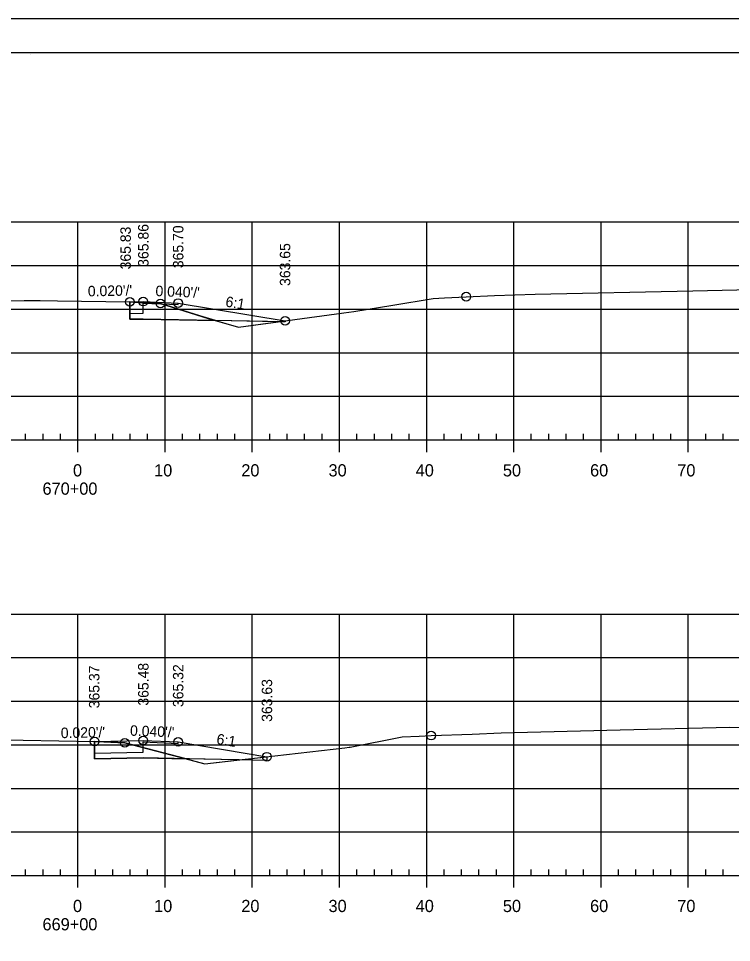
# Model space of a CAD drawing. Extents: x 1359801 to 1362404, y 372415 to 374228.
# Drawn here: x 1361813.1 to 1361894.9, y 373908.6 to 374014.6 of the extents above; entities that cross this region are included whole.
import ezdxf

# ---------------------------------------------------------------- set-up
doc = ezdxf.new("R2010")
doc.units = 0
for name, color, linetype in [('S_DRG_PT_SYM', 7, 'Continuous'), ('S_ELECTRIC_UTILITIES_ANNOT', 7, 'Continuous'), ('S_IRON_PIN', 7, 'Continuous'), ('S_MAILBOX', 7, 'Continuous'), ('S_PRIMARY_CTL', 7, 'Continuous'), ('S_SANITARY_SEWER', 7, 'Continuous'), ('S_SHOULDER', 7, 'Continuous'), ('S_UNDERGROUND_CABLE', 7, 'Continuous'), ('S_UTL_PT_SYM', 7, 'Continuous'), ('S_WATER_UTILITIES', 7, 'Continuous')]:
    doc.layers.add(name, color=color, linetype=linetype)

msp = doc.modelspace()

# ---------------------------------------------------------------- linework, layer by layer
at = {"layer": 'S_DRG_PT_SYM'}
for points in [[(1361805.02, 373982.16), (1361813.73, 373982.25), (1361815.57, 373982.27), (1361817.55, 373982.24), (1361825.85, 373982.1), (1361826.99, 373982.04), (1361829.35, 373981.92), (1361834.83, 373980.21), (1361838.31, 373979.2), (1361850.39, 373980.85), (1361851.53, 373981), (1361855.99, 373981.73), (1361860.64, 373982.48), (1361861.95, 373982.57), (1361864.43, 373982.7), (1361867.66, 373982.82), (1361872.35, 373982.98), (1361890.4, 373983.37), (1361898.81, 373983.56)], [(1361811.72, 373931.84), (1361813.61, 373931.8), (1361821.81, 373931.64), (1361822.85, 373931.6), (1361825.26, 373931.49), (1361831.41, 373929.89), (1361834.46, 373929.09), (1361850.51, 373930.92), (1361851.01, 373930.98), (1361851.1, 373930.99), (1361857.07, 373932.17), (1361859.03, 373932.26), (1361860.39, 373932.32), (1361865.12, 373932.5), (1361868.43, 373932.63), (1361882.09, 373932.98), (1361894.64, 373933.28), (1361902.31, 373933.15), (1361921.1, 373932.76), (1361940.7, 373933.16), (1361943.77, 373933.22), (1361944.16, 373933.23), (1361947.51, 373933.14), (1361964.89, 373932.7)]]:
    msp.add_lwpolyline(points, dxfattribs=at)
at = {"layer": 'S_ELECTRIC_UTILITIES_ANNOT'}
for p, q in [((1361833.88, 373980.5), (1361829.35, 373981.92)), ((1361842.87, 373979.82), (1361835.66, 373979.97)), ((1361835.66, 373979.97), (1361835.66, 373979.97)), ((1361842.87, 373979.82), (1361842.87, 373979.82)), ((1361832.3, 373929.66), (1361825.26, 373931.49)), ((1361838.4, 373929.54), (1361832.3, 373929.66)), ((1361832.3, 373929.66), (1361832.3, 373929.66)), ((1361838.4, 373929.54), (1361838.4, 373929.54))]:
    msp.add_line(p, q, dxfattribs=at)
for points in [[(1361829.35, 373981.92), (1361826.99, 373982.04), (1361825.85, 373982.1)], [(1361825.85, 373982.1), (1361825.85, 373980.6), (1361825.85, 373980.1), (1361827.39, 373980.13), (1361835.66, 373979.97), (1361833.88, 373980.5)], [(1361835.66, 373979.97), (1361838.31, 373979.2), (1361842.87, 373979.82)], [(1361825.26, 373931.49), (1361822.85, 373931.6), (1361821.81, 373931.64)], [(1361821.81, 373931.64), (1361821.81, 373929.64), (1361827.39, 373929.76), (1361832.3, 373929.66)], [(1361832.3, 373929.66), (1361834.46, 373929.09), (1361838.4, 373929.54)]]:
    msp.add_lwpolyline(points, dxfattribs=at)
for points in [[(1361842.87, 373979.82), (1361843.65, 373979.93), (1361843.65, 373979.81)], [(1361838.4, 373929.54), (1361841.57, 373929.9), (1361841.57, 373929.47)]]:
    msp.add_lwpolyline(points, close=True, dxfattribs=at)
at = {"layer": 'S_MAILBOX'}
for p, q in [((1361674.89, 373991.27), (1361964.89, 373991.27)), ((1361819.89, 373966.27), (1361819.89, 373991.27)), ((1361829.89, 373966.27), (1361829.89, 373991.27)), ((1361839.89, 373966.27), (1361839.89, 373991.27)), ((1361849.89, 373966.27), (1361849.89, 373991.27)), ((1361859.89, 373966.27), (1361859.89, 373991.27)), ((1361869.89, 373966.27), (1361869.89, 373991.27)), ((1361879.89, 373966.27), (1361879.89, 373991.27)), ((1361889.89, 373966.27), (1361889.89, 373991.27)), ((1361674.89, 373986.27), (1361964.89, 373986.27)), ((1361674.89, 373981.27), (1361964.89, 373981.27)), ((1361674.89, 373976.27), (1361964.89, 373976.27)), ((1361674.89, 373971.27), (1361964.89, 373971.27)), ((1361674.89, 373966.27), (1361964.89, 373966.27)), ((1361674.89, 373946.27), (1361964.89, 373946.27)), ((1361819.89, 373916.27), (1361819.89, 373946.27)), ((1361829.89, 373916.27), (1361829.89, 373946.27)), ((1361839.89, 373916.27), (1361839.89, 373946.27)), ((1361849.89, 373916.27), (1361849.89, 373946.27)), ((1361859.89, 373916.27), (1361859.89, 373946.27)), ((1361869.89, 373916.27), (1361869.89, 373946.27)), ((1361879.89, 373916.27), (1361879.89, 373946.27)), ((1361889.89, 373916.27), (1361889.89, 373946.27)), ((1361674.89, 373941.27), (1361964.89, 373941.27)), ((1361674.89, 373936.27), (1361964.89, 373936.27)), ((1361674.89, 373931.27), (1361964.89, 373931.27)), ((1361674.89, 373926.27), (1361964.89, 373926.27)), ((1361674.89, 373921.27), (1361964.89, 373921.27)), ((1361674.89, 373916.27), (1361964.89, 373916.27))]:
    msp.add_line(p, q, dxfattribs=at)
at = {"layer": 'S_SANITARY_SEWER'}
for points in [[(1361825.85, 373982.1), (1361827.39, 373982.13), (1361831.39, 373981.97), (1361843.65, 373979.93)], [(1361821.81, 373931.64), (1361827.39, 373931.76), (1361831.39, 373931.6), (1361841.57, 373929.9)]]:
    msp.add_lwpolyline(points, dxfattribs=at)
at = {"layer": 'S_SHOULDER'}
for p, q in [((1361649.49, 374014.63), (1361982.82, 374014.63)), ((1361843.65, 373979.93), (1361843.65, 373979.81)), ((1361843.65, 373979.81), (1361843.65, 373979.81)), ((1361841.57, 373929.9), (1361841.57, 373929.47)), ((1361841.57, 373929.47), (1361841.58, 373929.47))]:
    msp.add_line(p, q, dxfattribs=at)
for points in [[(1361649.48, 374014.63), (1361982.82, 374014.63), (1361982.82, 373801.29), (1361649.48, 373801.29)], [(1361895.81, 374010.73), (1361895.81, 374000.85), (1361931.54, 374000.85), (1361931.54, 373997.93), (1361954.74, 373997.93), (1361954.74, 373973.6), (1361978.07, 373973.6), (1361978.07, 373805.27), (1361661.89, 373805.27), (1361661.89, 374010.73)]]:
    msp.add_lwpolyline(points, close=True, dxfattribs=at)
for points in [[(1361825.85, 373980.77), (1361827.39, 373980.8), (1361827.39, 373981.96)], [(1361827.39, 373981.96), (1361831.37, 373981.8), (1361831.39, 373981.97), (1361843.65, 373979.93)], [(1361843.65, 373979.81), (1361827.39, 373980.13), (1361825.85, 373980.1), (1361825.85, 373980.77)], [(1361821.81, 373930.31), (1361827.39, 373930.42), (1361827.39, 373931.59)], [(1361827.39, 373931.59), (1361831.37, 373931.43), (1361831.39, 373931.6), (1361841.57, 373929.9)], [(1361841.58, 373929.47), (1361827.39, 373929.76), (1361821.81, 373929.64), (1361821.81, 373930.31)]]:
    msp.add_lwpolyline(points, dxfattribs=at)
for centre in [(1361864.43, 373982.7), (1361825.85, 373982.1), (1361827.39, 373982.13), (1361829.35, 373981.92), (1361831.39, 373981.97), (1361843.65, 373979.93), (1361821.81, 373931.64), (1361827.39, 373931.76), (1361860.39, 373932.32), (1361825.26, 373931.49), (1361831.39, 373931.6), (1361841.57, 373929.9)]:
    msp.add_circle(centre, 0.5, dxfattribs=at)
at = {"layer": 'S_UNDERGROUND_CABLE'}
for p, q in [((1361843.65, 373979.93), (1361843.65, 373979.81)), ((1361841.57, 373929.9), (1361841.57, 373929.47))]:
    msp.add_line(p, q, dxfattribs=at)
for points in [[(1361843.65, 373979.81), (1361827.39, 373980.13), (1361825.85, 373980.1), (1361825.85, 373982.1), (1361825.85, 373982.1)], [(1361841.58, 373929.47), (1361827.39, 373929.76), (1361821.81, 373929.64), (1361821.81, 373931.64), (1361821.81, 373931.64)]]:
    msp.add_lwpolyline(points, dxfattribs=at)
at = {"layer": 'S_UTL_PT_SYM'}
for p, q in [((1361661.89, 374010.73), (1361978.07, 374010.73)), ((1361814.41, 374010.47), (1361814.41, 374010.47)), ((1361814.41, 374010.47), (1361814.41, 374010.47))]:
    msp.add_line(p, q, dxfattribs=at)
at = {"layer": 'S_WATER_UTILITIES'}
for p, q in [((1361674.89, 373966.27), (1361964.89, 373966.27)), ((1361813.89, 373966.27), (1361813.89, 373966.97)), ((1361815.89, 373966.27), (1361815.89, 373966.97)), ((1361817.89, 373966.27), (1361817.89, 373966.97)), ((1361819.89, 373964.87), (1361819.89, 373966.27)), ((1361821.89, 373966.27), (1361821.89, 373966.97)), ((1361823.89, 373966.27), (1361823.89, 373966.97)), ((1361825.89, 373966.27), (1361825.89, 373966.97)), ((1361827.89, 373966.27), (1361827.89, 373966.97)), ((1361829.89, 373964.87), (1361829.89, 373966.27)), ((1361831.89, 373966.27), (1361831.89, 373966.97)), ((1361833.89, 373966.27), (1361833.89, 373966.97)), ((1361835.89, 373966.27), (1361835.89, 373966.97)), ((1361837.89, 373966.27), (1361837.89, 373966.97)), ((1361839.89, 373964.87), (1361839.89, 373966.27)), ((1361841.89, 373966.27), (1361841.89, 373966.97)), ((1361843.89, 373966.27), (1361843.89, 373966.97)), ((1361845.89, 373966.27), (1361845.89, 373966.97)), ((1361847.89, 373966.27), (1361847.89, 373966.97)), ((1361849.89, 373964.87), (1361849.89, 373966.27)), ((1361851.89, 373966.27), (1361851.89, 373966.97)), ((1361853.89, 373966.27), (1361853.89, 373966.97)), ((1361855.89, 373966.27), (1361855.89, 373966.97)), ((1361857.89, 373966.27), (1361857.89, 373966.97)), ((1361859.89, 373964.87), (1361859.89, 373966.27)), ((1361861.89, 373966.27), (1361861.89, 373966.97)), ((1361863.89, 373966.27), (1361863.89, 373966.97)), ((1361865.89, 373966.27), (1361865.89, 373966.97)), ((1361867.89, 373966.27), (1361867.89, 373966.97)), ((1361869.89, 373964.87), (1361869.89, 373966.27)), ((1361871.89, 373966.27), (1361871.89, 373966.97)), ((1361873.89, 373966.27), (1361873.89, 373966.97)), ((1361875.89, 373966.27), (1361875.89, 373966.97)), ((1361877.89, 373966.27), (1361877.89, 373966.97)), ((1361879.89, 373964.87), (1361879.89, 373966.27)), ((1361881.89, 373966.27), (1361881.89, 373966.97)), ((1361883.89, 373966.27), (1361883.89, 373966.97)), ((1361885.89, 373966.27), (1361885.89, 373966.97)), ((1361887.89, 373966.27), (1361887.89, 373966.97)), ((1361889.89, 373964.87), (1361889.89, 373966.27)), ((1361891.89, 373966.27), (1361891.89, 373966.97)), ((1361893.89, 373966.27), (1361893.89, 373966.97)), ((1361674.89, 373916.27), (1361964.89, 373916.27)), ((1361813.89, 373916.27), (1361813.89, 373916.97)), ((1361815.89, 373916.27), (1361815.89, 373916.97)), ((1361817.89, 373916.27), (1361817.89, 373916.97)), ((1361819.89, 373914.87), (1361819.89, 373916.27)), ((1361821.89, 373916.27), (1361821.89, 373916.97)), ((1361823.89, 373916.27), (1361823.89, 373916.97)), ((1361825.89, 373916.27), (1361825.89, 373916.97)), ((1361827.89, 373916.27), (1361827.89, 373916.97)), ((1361829.89, 373914.87), (1361829.89, 373916.27)), ((1361831.89, 373916.27), (1361831.89, 373916.97)), ((1361833.89, 373916.27), (1361833.89, 373916.97)), ((1361835.89, 373916.27), (1361835.89, 373916.97)), ((1361837.89, 373916.27), (1361837.89, 373916.97)), ((1361839.89, 373914.87), (1361839.89, 373916.27)), ((1361841.89, 373916.27), (1361841.89, 373916.97)), ((1361843.89, 373916.27), (1361843.89, 373916.97)), ((1361845.89, 373916.27), (1361845.89, 373916.97)), ((1361847.89, 373916.27), (1361847.89, 373916.97)), ((1361849.89, 373914.87), (1361849.89, 373916.27)), ((1361851.89, 373916.27), (1361851.89, 373916.97)), ((1361853.89, 373916.27), (1361853.89, 373916.97)), ((1361855.89, 373916.27), (1361855.89, 373916.97)), ((1361857.89, 373916.27), (1361857.89, 373916.97)), ((1361859.89, 373914.87), (1361859.89, 373916.27)), ((1361861.89, 373916.27), (1361861.89, 373916.97)), ((1361863.89, 373916.27), (1361863.89, 373916.97)), ((1361865.89, 373916.27), (1361865.89, 373916.97)), ((1361867.89, 373916.27), (1361867.89, 373916.97)), ((1361869.89, 373914.87), (1361869.89, 373916.27)), ((1361871.89, 373916.27), (1361871.89, 373916.97)), ((1361873.89, 373916.27), (1361873.89, 373916.97)), ((1361875.89, 373916.27), (1361875.89, 373916.97)), ((1361877.89, 373916.27), (1361877.89, 373916.97)), ((1361879.89, 373914.87), (1361879.89, 373916.27)), ((1361881.89, 373916.27), (1361881.89, 373916.97)), ((1361883.89, 373916.27), (1361883.89, 373916.97)), ((1361885.89, 373916.27), (1361885.89, 373916.97)), ((1361887.89, 373916.27), (1361887.89, 373916.97)), ((1361889.89, 373914.87), (1361889.89, 373916.27)), ((1361891.89, 373916.27), (1361891.89, 373916.97)), ((1361893.89, 373916.27), (1361893.89, 373916.97))]:
    msp.add_line(p, q, dxfattribs=at)

# ---------------------------------------------------------------- texts
at = {"layer": 'S_IRON_PIN'}
for s, rotation, p in [('365.83', 90, (1361825.96, 373985.83)), ('365.86', 90, (1361827.99, 373986.13)), ('365.70', 90, (1361831.99, 373985.97)), ('363.65', 90, (1361844.25, 373983.93)), ("0.020'/'", 1.1458, (1361821.04, 373982.73)), ("0.040'/'", 357.7094, (1361828.77, 373982.77)), ('6:1', 350.5377, (1361836.75, 373981.58)), ('365.37', 90, (1361822.36, 373935.46)), ('365.48', 90, (1361827.99, 373935.76)), ('365.32', 90, (1361831.99, 373935.6)), ('363.63', 90, (1361842.17, 373933.9)), ("0.020'/'", 1.1458, (1361817.94, 373932.03)), ("0.040'/'", 357.7094, (1361825.85, 373932.32)), ('6:1', 350.5377, (1361835.72, 373931.38))]:
    msp.add_text(s, height=1.2, rotation=rotation, dxfattribs=at).set_placement(p)
at = {"layer": 'S_PRIMARY_CTL'}
for s, p in [('0', (1361819.33, 373962.07)), ('10', (1361828.63, 373962.07)), ('20', (1361838.63, 373962.07)), ('30', (1361848.63, 373962.07)), ('40', (1361858.63, 373962.07)), ('50', (1361868.63, 373962.07)), ('60', (1361878.63, 373962.07)), ('70', (1361888.63, 373962.07)), ('670+00', (1361815.83, 373959.97)), ('0', (1361819.33, 373912.07)), ('10', (1361828.63, 373912.07)), ('20', (1361838.63, 373912.07)), ('30', (1361848.63, 373912.07)), ('40', (1361858.63, 373912.07)), ('50', (1361868.63, 373912.07)), ('60', (1361878.63, 373912.07)), ('70', (1361888.63, 373912.07)), ('669+00', (1361815.83, 373909.97))]:
    msp.add_text(s, height=1.4, dxfattribs=at).set_placement(p)
at = {"layer": 'S_SHOULDER'}
for p in [(1361872.3, 373982.93), (1361868.38, 373932.58)]:
    msp.add_text('+', height=0.1, dxfattribs=at).set_placement(p)

doc.saveas('drawing.dxf')
